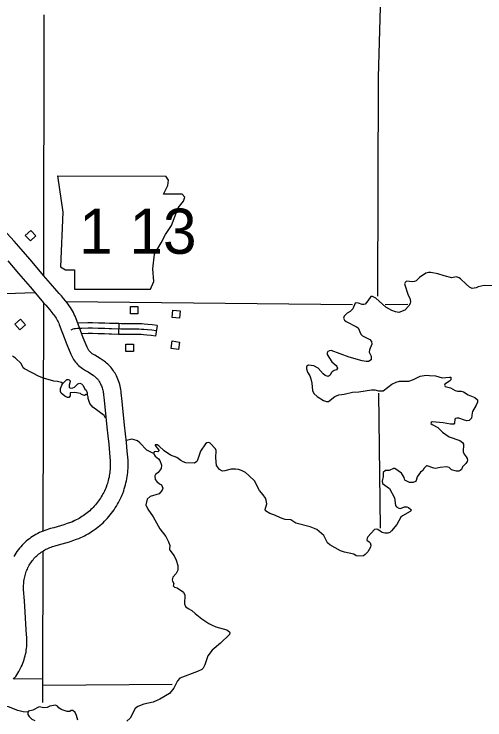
# Model space of a CAD drawing. Extents: x -19 to 366, y -4 to 359.
# Drawn here: x 133.386 to 134.638, y 199.977 to 201.853 of the extents above; entities that cross this region are included whole.
import ezdxf

# ---------------------------------------------------------------- set-up
doc = ezdxf.new("R2010")
doc.units = 0
for name, color, linetype in [('Level 10', 7, 'Continuous'), ('Level 21', 7, 'Continuous'), ('Level 32', 7, 'Continuous'), ('Level 35', 7, 'Continuous'), ('Level 4', 7, 'Continuous'), ('Level 5', 7, 'Continuous'), ('Level 56', 7, 'Continuous'), ('Level 60', 7, 'Continuous'), ('Level 9', 7, 'Continuous')]:
    doc.layers.add(name, color=color, linetype=linetype)

msp = doc.modelspace()

# ---------------------------------------------------------------- linework, layer by layer
at = {"layer": 'Level 10'}
for p, q in [((133.5147, 201.0049), (133.5148, 201.0049)), ((133.5432, 200.5044), (133.5437, 200.5046))]:
    msp.add_line(p, q, dxfattribs=at)
for points in [[(133.5591, 201.0214), (133.5575, 201.0258), (133.5501, 201.0452), (133.5482, 201.05), (133.546, 201.0548), (133.5436, 201.0595), (133.5412, 201.0642), (133.5385, 201.0687), (133.5358, 201.0732), (133.5329, 201.0776), (133.5298, 201.0819), (133.5266, 201.086), (133.5235, 201.0898), (133.5178, 201.0967), (133.512, 201.1037), (133.5059, 201.1106), (133.5, 201.1172), (133.4831, 201.1365), (133.4646, 201.1583), (133.434, 201.1941), (133.4051, 201.2284), (133.3865, 201.2494), (133.3581, 201.2803)], [(133.3693, 201.1975), (133.3979, 201.1635), (133.4285, 201.1277), (133.4472, 201.1055), (133.4647, 201.0857), (133.4705, 201.0792), (133.476, 201.0729), (133.4814, 201.0665), (133.4868, 201.0598), (133.4894, 201.0566), (133.4917, 201.0537), (133.4939, 201.0507), (133.4959, 201.0476), (133.4979, 201.0444), (133.4998, 201.0412), (133.5015, 201.0379), (133.5032, 201.0346), (133.5047, 201.0312), (133.5061, 201.0277), (133.5132, 201.0091), (133.5147, 201.0049)], [(133.5148, 201.0049), (133.5261, 200.9747), (133.5367, 200.9488), (133.5383, 200.9453), (133.5401, 200.9416), (133.5421, 200.938), (133.5444, 200.9344), (133.5467, 200.9311), (133.5492, 200.9278), (133.5519, 200.9247), (133.5547, 200.9217), (133.5576, 200.9188), (133.5607, 200.916), (133.564, 200.9135), (133.5677, 200.9108), (133.5757, 200.906), (133.5826, 200.9017), (133.5896, 200.8973), (133.5961, 200.893), (133.5979, 200.8918), (133.5996, 200.8905), (133.6013, 200.8891), (133.6029, 200.8876), (133.6045, 200.8861), (133.606, 200.8846), (133.6074, 200.883), (133.6088, 200.8813), (133.6102, 200.8796), (133.6114, 200.8778), (133.6126, 200.876), (133.6138, 200.8741), (133.6148, 200.8723), (133.6158, 200.8704), (133.617, 200.8677), (133.6182, 200.8649), (133.6193, 200.862), (133.6203, 200.8591), (133.6211, 200.8561), (133.6219, 200.8531), (133.6226, 200.8501), (133.6231, 200.847), (133.6236, 200.844), (133.6239, 200.8408), (133.6252, 200.827), (133.6327, 200.7549), (133.6353, 200.7321), (133.6376, 200.7095), (133.6397, 200.6868), (133.6416, 200.6645), (133.6418, 200.6605), (133.6418, 200.6562), (133.6418, 200.6518), (133.6416, 200.6475), (133.6414, 200.6432), (133.641, 200.639), (133.6405, 200.6347), (133.6399, 200.6304), (133.6392, 200.6261), (133.6384, 200.6219), (133.6374, 200.6177), (133.6364, 200.6135), (133.6353, 200.6093), (133.634, 200.6053), (133.6327, 200.6013), (133.6306, 200.5956), (133.6296, 200.5931), (133.628, 200.5891), (133.6262, 200.5852), (133.6244, 200.5815), (133.6224, 200.5777), (133.6202, 200.5738), (133.6179, 200.57), (133.6155, 200.5662), (133.613, 200.5625), (133.6104, 200.5588), (133.6077, 200.5552), (133.6049, 200.5517), (133.6021, 200.5482), (133.5991, 200.5449), (133.5961, 200.5415), (133.5932, 200.5385), (133.5902, 200.5357), (133.587, 200.5327), (133.5837, 200.5299), (133.5804, 200.5271), (133.5769, 200.5245), (133.5735, 200.5219), (133.5699, 200.5194), (133.5663, 200.517), (133.5626, 200.5147), (133.5589, 200.5124), (133.5551, 200.5103), (133.5513, 200.5083), (133.5474, 200.5064), (133.5432, 200.5044)], [(133.5632, 200.4615), (133.5679, 200.4637), (133.5729, 200.4662), (133.5778, 200.4688), (133.5826, 200.4715), (133.5873, 200.4743), (133.592, 200.4772), (133.5966, 200.4803), (133.6012, 200.4835), (133.6056, 200.4868), (133.6099, 200.4902), (133.6142, 200.4937), (133.6184, 200.4973), (133.6225, 200.501), (133.6267, 200.505), (133.6307, 200.5092), (133.6345, 200.5134), (133.6382, 200.5177), (133.6418, 200.522), (133.6453, 200.5265), (133.6487, 200.531), (133.6519, 200.5356), (133.6551, 200.5403), (133.6581, 200.5451), (133.6611, 200.5499), (133.6638, 200.5549), (133.6666, 200.56), (133.6691, 200.5652), (133.6714, 200.5702), (133.6735, 200.5754), (133.6749, 200.5789), (133.6774, 200.5856), (133.6791, 200.5909), (133.6808, 200.5962), (133.6822, 200.6015), (133.6835, 200.6069), (133.6847, 200.6123), (133.6858, 200.6177), (133.6867, 200.6232), (133.6875, 200.6287), (133.6881, 200.6341), (133.6886, 200.6396), (133.6889, 200.6452), (133.6891, 200.6507), (133.6892, 200.6562), (133.6891, 200.6617), (133.6889, 200.6675), (133.6869, 200.691), (133.6847, 200.7141), (133.6824, 200.7371), (133.6798, 200.76), (133.6723, 200.8316), (133.671, 200.8455), (133.6705, 200.85), (133.6698, 200.8548), (133.669, 200.8595), (133.668, 200.8641), (133.6668, 200.8687), (133.6654, 200.8733), (133.6639, 200.8778), (133.6623, 200.8822), (133.6604, 200.8867), (133.6584, 200.8911), (133.6565, 200.8947), (133.6546, 200.8982), (133.6525, 200.9015), (133.6504, 200.9048), (133.6481, 200.9079), (133.6457, 200.911), (133.6432, 200.914), (133.6406, 200.9169), (133.6378, 200.9198), (133.635, 200.9225), (133.6321, 200.9251), (133.629, 200.9276), (133.6259, 200.93), (133.6227, 200.9322), (133.6151, 200.9372), (133.6077, 200.9418), (133.6003, 200.9464), (133.5939, 200.9503), (133.5927, 200.9511), (133.5912, 200.9523), (133.5899, 200.9535), (133.5885, 200.9548), (133.5873, 200.9562), (133.5861, 200.9576), (133.5849, 200.9591), (133.5838, 200.9607), (133.5828, 200.9622), (133.5819, 200.9638), (133.5811, 200.9655), (133.5802, 200.9674), (133.5701, 200.992), (133.5591, 201.0214)], [(133.5437, 200.5046), (133.5395, 200.5028), (133.5359, 200.5013), (133.5276, 200.4985), (133.5187, 200.4957), (133.5098, 200.4929), (133.5008, 200.4902), (133.4918, 200.4877), (133.4826, 200.4852), (133.4779, 200.4839), (133.4729, 200.4823), (133.4679, 200.4806), (133.4631, 200.4787), (133.4582, 200.4766), (133.4535, 200.4745), (133.4488, 200.4721), (133.4443, 200.4696), (133.4398, 200.467), (133.4354, 200.4642), (133.431, 200.4613), (133.4268, 200.4582), (133.4227, 200.455), (133.4186, 200.4516), (133.4148, 200.4482), (133.411, 200.4446), (133.4073, 200.4408), (133.4037, 200.437), (133.4003, 200.4331), (133.3969, 200.4289), (133.3937, 200.4244), (133.3907, 200.4201), (133.3879, 200.4157), (133.3853, 200.4112)], [(133.3845, 200.0846), (133.3875, 200.0885), (133.3904, 200.0924), (133.3932, 200.0965), (133.3959, 200.1007), (133.3985, 200.105), (133.4009, 200.1093), (133.4032, 200.1138), (133.4053, 200.1182), (133.4073, 200.1226), (133.4092, 200.1273), (133.411, 200.1321), (133.4127, 200.1369), (133.4142, 200.1418), (133.4156, 200.1468), (133.4167, 200.1518), (133.4178, 200.1568), (133.4186, 200.1618), (133.4193, 200.1669), (133.4198, 200.1721), (133.4202, 200.1771), (133.4204, 200.1823), (133.4204, 200.1875), (133.4203, 200.1925), (133.42, 200.1977), (133.4195, 200.2021), (133.4175, 200.2323), (133.4154, 200.2628), (133.4135, 200.2932), (133.4115, 200.3235), (133.4114, 200.3274), (133.4113, 200.3311), (133.4114, 200.3348), (133.4116, 200.3385), (133.4119, 200.3422), (133.4123, 200.3459), (133.4128, 200.3496), (133.4135, 200.3532), (133.4143, 200.3568), (133.4152, 200.3604), (133.4162, 200.364), (133.4173, 200.3675), (133.4185, 200.371), (133.4199, 200.3744), (133.4213, 200.3778), (133.4229, 200.3812), (133.4246, 200.3845), (133.4264, 200.3877), (133.4283, 200.3909), (133.4303, 200.3941), (133.4323, 200.3971), (133.4344, 200.3999), (133.4366, 200.4026), (133.439, 200.4054), (133.4415, 200.4081), (133.4441, 200.4107), (133.4468, 200.4132), (133.4495, 200.4157), (133.4523, 200.4181), (133.4552, 200.4203), (133.4582, 200.4225), (133.4613, 200.4246), (133.4644, 200.4265), (133.4676, 200.4284), (133.4708, 200.4302), (133.4741, 200.4318), (133.4775, 200.4334), (133.4808, 200.4348), (133.4843, 200.4361), (133.4878, 200.4373), (133.4913, 200.4384), (133.4951, 200.4395), (133.5045, 200.4421), (133.514, 200.4448), (133.5235, 200.4476), (133.533, 200.4505), (133.5424, 200.4536), (133.5524, 200.4569), (133.5579, 200.4592), (133.5632, 200.4615)]]:
    msp.add_lwpolyline(points, dxfattribs=at)
at = {"layer": 'Level 21'}
for p, q in [((133.5016, 201.4227), (133.516, 201.3266)), ((133.7963, 201.4115), (133.7897, 201.4226)), ((133.7947, 201.3971), (133.7963, 201.4115)), ((133.7835, 201.3746), (133.7947, 201.3971)), ((133.8332, 201.3746), (133.7835, 201.3746)), ((133.8396, 201.3666), (133.8332, 201.3746)), ((133.8364, 201.3554), (133.8396, 201.3666)), ((133.822, 201.3378), (133.8364, 201.3554)), ((133.516, 201.3266), (133.5096, 201.1808)), ((133.814, 201.317), (133.822, 201.3378)), ((133.8043, 201.2913), (133.814, 201.317)), ((133.7883, 201.2673), (133.8043, 201.2913)), ((133.7771, 201.2449), (133.7883, 201.2673)), ((133.7595, 201.2144), (133.7771, 201.2449)), ((133.7547, 201.176), (133.7595, 201.2144)), ((133.5096, 201.1808), (133.5224, 201.1728)), ((133.7579, 201.1423), (133.7547, 201.176)), ((133.5224, 201.1728), (133.5464, 201.1728)), ((133.5464, 201.1728), (133.5464, 201.1215)), ((133.7483, 201.1215), (133.7579, 201.1423)), ((133.5464, 201.1215), (133.7483, 201.1215))]:
    msp.add_line(p, q, dxfattribs=at)
msp.add_lwpolyline([(133.5016, 201.4227), (133.7897, 201.4226)], dxfattribs=at)
at = {"layer": 'Level 32'}
for p, q in [((133.6649, 201.0301), (133.664, 201.0017)), ((133.7663, 201.0252), (133.7621, 200.9971))]:
    msp.add_line(p, q, dxfattribs=at)
for points in [[(133.6649, 201.0301), (133.6455, 201.0307), (133.6394, 201.0308), (133.6276, 201.0312), (133.6101, 201.0318), (133.5944, 201.0323), (133.5824, 201.032), (133.5555, 201.0311)], [(133.7663, 201.0252), (133.7535, 201.0271), (133.7414, 201.028), (133.7323, 201.0288), (133.7256, 201.0292), (133.718, 201.0298), (133.7108, 201.0294), (133.6989, 201.0293), (133.6855, 201.0297), (133.6704, 201.0299), (133.6649, 201.0301)], [(133.7642, 201.0112), (133.7519, 201.013), (133.7403, 201.0138), (133.7312, 201.0146), (133.7246, 201.015), (133.7178, 201.0155), (133.7112, 201.0152), (133.6987, 201.0151), (133.6852, 201.0155), (133.6701, 201.0157), (133.6451, 201.0165), (133.639, 201.0166), (133.6271, 201.017), (133.6096, 201.0176), (133.5944, 201.0181), (133.5828, 201.0178), (133.5662, 201.0173), (133.5544, 201.0168), (133.5489, 201.0167), (133.5458, 201.0162), (133.5423, 201.0155), (133.5369, 201.0132)], [(133.664, 201.0017), (133.6448, 201.0023), (133.6387, 201.0024), (133.6266, 201.0028), (133.6091, 201.0034), (133.5944, 201.0039), (133.5832, 201.0036), (133.566, 201.003)], [(133.7621, 200.9971), (133.7504, 200.9989), (133.7392, 200.9997), (133.7301, 201.0004), (133.7236, 201.0009), (133.7176, 201.0013), (133.7116, 201.001), (133.6986, 201.0009), (133.6849, 201.0013), (133.6697, 201.0015), (133.664, 201.0017)]]:
    msp.add_lwpolyline(points, dxfattribs=at)
at = {"layer": 'Level 35'}
for points in [[(133.6295, 200.779), (133.6252, 200.7858), (133.5957, 200.8081), (133.5876, 200.8179), (133.5833, 200.8311), (133.5832, 200.8353), (133.5805, 200.8413), (133.5774, 200.8416), (133.5737, 200.8393), (133.5657, 200.8422), (133.5623, 200.8445), (133.5474, 200.8473), (133.5365, 200.8464), (133.5354, 200.846), (133.5351, 200.8384), (133.5314, 200.8338), (133.528, 200.8341), (133.5211, 200.837), (133.5115, 200.8449), (133.5096, 200.8494), (133.5094, 200.8577), (133.5131, 200.8669), (133.516, 200.8707), (133.5118, 200.8733), (133.5012, 200.8762), (133.4913, 200.8772), (133.4643, 200.8856), (133.4529, 200.8896), (133.4136, 200.9103), (133.4106, 200.9129), (133.4047, 200.9238), (133.3901, 200.938), (133.3817, 200.944)], [(133.516, 200.8707), (133.522, 200.8776), (133.5261, 200.8815), (133.5299, 200.8819), (133.5329, 200.8805), (133.5349, 200.8782), (133.5353, 200.8763), (133.5324, 200.8664), (133.5325, 200.8615), (133.5352, 200.8585), (133.5423, 200.8593), (133.5465, 200.8613), (133.5558, 200.8698), (133.5607, 200.8717), (133.5653, 200.8699), (133.5699, 200.8654), (133.5738, 200.856), (133.5773, 200.8534), (133.58, 200.8458), (133.5805, 200.8413)], [(133.7566, 200.6852), (133.7394, 200.6941), (133.7206, 200.7131), (133.7141, 200.7184), (133.703, 200.7224), (133.6992, 200.7227), (133.6847, 200.7196)], [(133.4228, 199.9971), (133.4101, 199.9985), (133.3961, 200.0021), (133.3708, 200.0115), (133.3654, 200.0125), (133.3537, 200.0117), (133.3444, 200.0093), (133.3194, 199.9973), (133.3008, 199.9924), (133.2681, 199.9889), (133.2344, 199.9947), (133.2202, 199.9964), (133.2036, 199.9948), (133.1897, 199.9976)]]:
    msp.add_lwpolyline(points, dxfattribs=at)
at = {"layer": 'Level 4'}
for points in [[(133.4656, 201.1592), (133.4657, 201.8513)], [(133.4636, 200.4803), (133.4655, 201.0842)], [(133.4629, 200.0226), (133.4622, 200.0687), (133.4623, 200.087), (133.4634, 200.4243)]]:
    msp.add_lwpolyline(points, dxfattribs=at)
at = {"layer": 'Level 5'}
for points in [[(134.3528, 201.1029), (134.3551, 201.6851), (134.3662, 202.0884)], [(133.4403, 201.112), (132.4715, 201.0786)], [(133.5248, 201.0893), (134.2853, 201.0812)], [(134.3728, 201.081), (134.4331, 201.0823)], [(134.36, 200.4867), (134.3556, 200.8454)], [(133.3863, 200.0855), (133.4623, 200.087)], [(133.4622, 200.0687), (133.8062, 200.0715)]]:
    msp.add_lwpolyline(points, dxfattribs=at)
at = {"layer": 'Level 56'}
for points in [[(133.4438, 201.2636), (133.4295, 201.25), (133.4159, 201.2644), (133.4303, 201.2779)], [(133.6955, 201.0559), (133.6955, 201.0756), (133.7152, 201.0756), (133.7152, 201.0559)], [(133.8061, 201.0468), (133.808, 201.0664), (133.8277, 201.0645), (133.8258, 201.0449)], [(133.4032, 201.0417), (133.4162, 201.0269), (133.4013, 201.0138), (133.3883, 201.0287)], [(133.6833, 200.9559), (133.6833, 200.9756), (133.7031, 200.9756), (133.7031, 200.9559)], [(133.8233, 200.9617), (133.8038, 200.9645), (133.8066, 200.9841), (133.8261, 200.9813)]]:
    msp.add_lwpolyline(points, close=True, dxfattribs=at)
at = {"layer": 'Level 60'}
for points in [[(139.4406, 1.5315), (139.2511, 10.1473), (139.0608, 18.7633), (138.8699, 27.3793), (138.6784, 35.9956), (138.4861, 44.6119), (138.2932, 53.2285), (138.0997, 61.8451), (137.9055, 70.4619), (137.7106, 79.0789), (137.5151, 87.6959), (137.319, 96.3132), (137.1221, 104.9306), (136.9247, 113.5481), (136.7265, 122.1658), (136.5278, 130.7836), (136.3283, 139.4016), (136.1282, 148.0197), (135.9275, 156.6379), (135.7261, 165.2564), (135.5241, 173.8749), (135.3214, 182.4936), (135.1181, 191.1125), (134.9141, 199.7315), (134.7095, 208.3506), (134.5043, 216.9699), (134.2984, 225.5894), (134.0919, 234.209), (133.8847, 242.8288), (133.6769, 251.4487), (133.4685, 260.0687), (133.2594, 268.6889), (133.0497, 277.3093), (132.8393, 285.9298), (132.6283, 294.5504), (132.4167, 303.1713), (132.2044, 311.7922), (131.9916, 320.4133), (131.778, 329.0346), (131.5639, 337.656), (131.3491, 346.2776)], [(0, 198.1326), (7.1014, 198.137), (14.2028, 198.1503), (21.3042, 198.1724), (28.4055, 198.2034), (35.5068, 198.2433), (42.6081, 198.292), (49.7092, 198.3496), (56.8103, 198.4161), (63.9113, 198.4913), (71.0123, 198.5755), (78.1131, 198.6685), (85.2137, 198.7704), (92.3143, 198.8811), (99.4147, 199.0007), (106.5149, 199.1291), (113.615, 199.2664), (120.7149, 199.4126), (127.8146, 199.5676), (134.9141, 199.7315), (142.0135, 199.9042), (149.1125, 200.0858), (156.2114, 200.2762), (163.31, 200.4755), (170.4084, 200.6837), (177.5065, 200.9007), (184.6043, 201.1265), (191.7018, 201.3612), (198.799, 201.6048), (205.896, 201.8572), (212.9926, 202.1185), (220.0888, 202.3886), (227.1848, 202.6676), (234.2803, 202.9554), (241.3755, 203.2521), (248.4704, 203.5576), (255.5648, 203.872), (262.6589, 204.1952), (269.7525, 204.5273), (276.8457, 204.8682), (283.9385, 205.218), (291.0309, 205.5766), (298.1228, 205.9441), (305.2142, 206.3204), (312.3051, 206.7056), (319.3956, 207.0996), (326.4856, 207.5024), (333.5751, 207.9141), (340.664, 208.3347)]]:
    msp.add_spline(points, degree=3, dxfattribs=at)
at = {"layer": 'Level 9'}
for points in [[(134.6609, 201.1304), (134.6359, 201.1312), (134.6197, 201.1279), (134.6141, 201.1252), (134.6035, 201.1235), (134.5966, 201.1272), (134.5874, 201.1347), (134.5732, 201.1489), (134.569, 201.1519), (134.5614, 201.1544), (134.5497, 201.152), (134.5295, 201.157), (134.5128, 201.1628), (134.4942, 201.1664), (134.4881, 201.1659), (134.4802, 201.1639), (134.4634, 201.1526), (134.4548, 201.1442), (134.4507, 201.1422), (134.4454, 201.1414), (134.4291, 201.1427), (134.4253, 201.1392), (134.4243, 201.1362), (134.4334, 201.1059), (134.4377, 201.0977), (134.4397, 201.089), (134.4391, 201.0836), (134.4357, 201.0771), (134.4249, 201.066), (134.4088, 201.0601), (134.3997, 201.0611), (134.3905, 201.0651)], [(134.3905, 201.0651), (134.3745, 201.0736), (134.348, 201.0979), (134.3388, 201.102), (134.3343, 201.1019), (134.3265, 201.0908), (134.3191, 201.0823), (134.3157, 201.0808), (134.3115, 201.0807), (134.3013, 201.0847), (134.2971, 201.0854), (134.2926, 201.0842), (134.2867, 201.0694), (134.2793, 201.0624), (134.2718, 201.0581), (134.2639, 201.0497), (134.2617, 201.0443), (134.2645, 201.0395), (134.2687, 201.0357), (134.2965, 201.0221), (134.3011, 201.0187), (134.3078, 201.0021), (134.312, 200.9976), (134.3315, 200.9877), (134.3361, 200.9824), (134.3374, 200.976), (134.3308, 200.9607), (134.3301, 200.9543), (134.3352, 200.9433), (134.3357, 200.9369), (134.335, 200.9342), (134.3279, 200.9292), (134.3218, 200.9291), (134.3112, 200.9312), (134.2766, 200.9406), (134.2286, 200.9585), (134.2241, 200.9581), (134.2203, 200.9561), (134.2185, 200.9527), (134.2182, 200.9481), (134.2306, 200.9286), (134.2425, 200.9193), (134.2444, 200.9163), (134.2456, 200.9121), (134.243, 200.9071), (134.2366, 200.9055), (134.2314, 200.9024), (134.2291, 200.8997), (134.2262, 200.8929), (134.2213, 200.8894), (134.213, 200.8919), (134.208, 200.8964), (134.1945, 200.9114), (134.1827, 200.918), (134.169, 200.9201), (134.1645, 200.9174), (134.1634, 200.9155), (134.1631, 200.9098), (134.1659, 200.9015), (134.1721, 200.891), (134.1752, 200.8838), (134.1777, 200.8717), (134.1791, 200.8527)], [(134.1791, 200.8527), (134.183, 200.8441), (134.1915, 200.8366), (134.2087, 200.8258), (134.2167, 200.8229), (134.222, 200.8234), (134.2384, 200.8361), (134.2497, 200.8405), (134.2637, 200.8425), (134.2856, 200.8482), (134.3022, 200.8492), (134.3362, 200.8538), (134.3453, 200.8539), (134.3552, 200.8518), (134.3673, 200.8516), (134.3905, 200.8694), (134.4014, 200.8748), (134.4108, 200.8769), (134.435, 200.8772), (134.4478, 200.8819), (134.4658, 200.8905), (134.4813, 200.8934), (134.4901, 200.892), (134.506, 200.8915), (134.5238, 200.886), (134.5439, 200.8882), (134.5473, 200.8875), (134.547, 200.8807), (134.5433, 200.8768), (134.5313, 200.8695), (134.5306, 200.8664), (134.5321, 200.863), (134.5458, 200.8594), (134.5584, 200.852), (134.5649, 200.8502), (134.5747, 200.8507), (134.5804, 200.8493), (134.593, 200.8411), (134.6113, 200.8342), (134.6182, 200.8274), (134.6176, 200.821), (134.6147, 200.813), (134.6051, 200.7969), (134.6036, 200.7927), (134.6016, 200.7786), (134.596, 200.7725), (134.5899, 200.772), (134.5835, 200.7731), (134.5686, 200.7785), (134.5626, 200.7792), (134.5595, 200.7784), (134.5577, 200.7761), (134.5571, 200.7655), (134.5549, 200.7632), (134.5461, 200.7631), (134.5264, 200.7666), (134.4972, 200.7692), (134.4946, 200.7673), (134.4943, 200.765), (134.4973, 200.7624), (134.5122, 200.7539), (134.5245, 200.7415), (134.5429, 200.7296), (134.5707, 200.7198)], [(133.8357, 200.6628), (133.8296, 200.6661), (133.8185, 200.6747), (133.8021, 200.6809), (133.7849, 200.6924), (133.7711, 200.7051), (133.7661, 200.7081), (133.7615, 200.708), (133.7608, 200.7061), (133.7705, 200.6934), (133.7705, 200.6918), (133.7683, 200.6895), (133.7626, 200.6906), (133.7584, 200.689), (133.7566, 200.6852), (133.7609, 200.6777), (133.7697, 200.6706), (133.7735, 200.6661), (133.7783, 200.654), (133.7773, 200.6453), (133.7695, 200.6345), (133.762, 200.6287), (133.7602, 200.6253), (133.7611, 200.6158), (133.7657, 200.6102), (133.7726, 200.6042), (133.7779, 200.6013), (133.7815, 200.593), (133.78, 200.5876), (133.7715, 200.578), (133.7474, 200.5709), (133.7399, 200.5632), (133.7367, 200.5487), (133.7418, 200.5366), (133.7561, 200.5164), (133.7733, 200.4847), (133.7895, 200.4641), (133.7969, 200.4502), (133.7997, 200.4403), (133.7991, 200.4305), (133.8003, 200.4278), (133.8118, 200.4132), (133.8173, 200.4015), (133.8217, 200.3875), (133.8211, 200.3746), (133.8171, 200.3655), (133.8078, 200.3559), (133.806, 200.3494), (133.8072, 200.3452), (133.8111, 200.3396), (133.8093, 200.3327), (133.8127, 200.3294), (133.8196, 200.3279), (133.8368, 200.3164), (133.8399, 200.3085), (133.8395, 200.2854), (133.8419, 200.2782), (133.8488, 200.273), (133.8587, 200.2678), (133.8676, 200.2596), (133.8856, 200.2454), (133.9039, 200.2328), (133.9112, 200.2291)], [(134.3593, 200.4786), (134.3528, 200.483), (134.3483, 200.4841), (134.3441, 200.4833), (134.3266, 200.4637), (134.3244, 200.4595), (134.3241, 200.4542), (134.3302, 200.4501), (134.3322, 200.4474), (134.3342, 200.441), (134.3331, 200.4357), (134.3265, 200.4231), (134.319, 200.4162), (134.3145, 200.4131), (134.3009, 200.4121), (134.2956, 200.4132), (134.2895, 200.4169), (134.2644, 200.4226), (134.2541, 200.4259), (134.2251, 200.4421), (134.219, 200.4478), (134.2096, 200.467), (134.1912, 200.483), (134.1729, 200.49), (134.1349, 200.4997), (134.1219, 200.5082), (134.1071, 200.5099), (134.0984, 200.5124), (134.0763, 200.522), (134.0656, 200.5256), (134.0546, 200.5323), (134.0534, 200.5357), (134.0581, 200.551), (134.056, 200.5612), (134.054, 200.5665), (134.0482, 200.5747), (134.0386, 200.5863), (134.025, 200.6119), (134.0103, 200.6265), (134.0011, 200.634), (133.9908, 200.6399), (133.9825, 200.6425), (133.9745, 200.6435), (133.9632, 200.6433), (133.9462, 200.6385), (133.9401, 200.6377), (133.9318, 200.6421), (133.9244, 200.653), (133.9226, 200.6731), (133.923, 200.6925), (133.9214, 200.6974), (133.9072, 200.7127), (133.9034, 200.7142), (133.8985, 200.7134), (133.8947, 200.7107), (133.8818, 200.6911), (133.8738, 200.6671), (133.8716, 200.6633), (133.866, 200.6594), (133.8425, 200.6598), (133.8357, 200.6628)], [(134.5707, 200.7198), (134.5783, 200.7142), (134.5803, 200.71), (134.5802, 200.6892), (134.5826, 200.6828), (134.588, 200.6764), (134.5907, 200.6715), (134.5915, 200.6673), (134.5904, 200.6639), (134.5871, 200.6585), (134.5785, 200.6497), (134.5752, 200.6428), (134.5723, 200.6394), (134.5685, 200.6378), (134.5621, 200.6377), (134.5491, 200.6413), (134.5426, 200.6477), (134.5358, 200.6499), (134.5191, 200.6473), (134.5067, 200.6453), (134.5018, 200.6456), (134.4842, 200.6525), (134.482, 200.6525), (134.4764, 200.646), (134.4723, 200.6399), (134.4667, 200.6352), (134.4578, 200.6233), (134.4546, 200.6131), (134.4527, 200.6108), (134.4467, 200.6076), (134.4369, 200.6079), (134.425, 200.6142), (134.4234, 200.621), (134.4156, 200.633), (134.3981, 200.6449), (134.395, 200.6452), (134.3834, 200.6401), (134.3735, 200.6396), (134.3676, 200.6346), (134.367, 200.624), (134.3641, 200.6114), (134.365, 200.6053), (134.3837, 200.5923), (134.397, 200.5675), (134.4003, 200.547), (134.4023, 200.5429), (134.4088, 200.5392), (134.4133, 200.5389), (134.4238, 200.5428), (134.4303, 200.5429), (134.4345, 200.5414), (134.441, 200.5359), (134.4425, 200.534), (134.4388, 200.5305), (134.4189, 200.5196), (134.4144, 200.5158), (134.4034, 200.4962), (134.3892, 200.4794), (134.3847, 200.4751), (134.3799, 200.4728), (134.3719, 200.473), (134.3647, 200.4748), (134.3593, 200.4786)], [(133.9112, 200.2291), (133.9222, 200.2239), (133.9515, 200.216), (133.9591, 200.2112), (133.9599, 200.2085), (133.9585, 200.2039), (133.9346, 200.1808), (133.9122, 200.1619), (133.9007, 200.147), (133.8927, 200.123), (133.8887, 200.1146), (133.8853, 200.1111), (133.8737, 200.1053), (133.827, 200.0875), (133.8207, 200.081), (133.8104, 200.0611), (133.7989, 200.0473), (133.7738, 200.0314), (133.7561, 200.0239), (133.7308, 200.0186), (133.715, 200.0124), (133.7083, 200.0066), (133.695, 199.9813), (133.6861, 199.9729)], [(133.5554, 199.9763), (133.5522, 199.9884), (133.5483, 199.9964), (133.5426, 200.0016), (133.538, 200.0015), (133.5343, 199.9992), (133.5275, 199.9987), (133.5111, 200.0046), (133.505, 200.009), (133.5015, 200.0131), (133.4965, 200.0161), (133.4811, 200.0132), (133.4739, 200.0093), (133.4648, 200.0092), (133.4527, 200.0113), (133.4362, 200.0027), (133.4245, 199.9995), (133.4226, 199.9972), (133.4227, 199.9912), (133.4262, 199.9855), (133.4335, 199.9784), (133.4408, 199.9747)]]:
    msp.add_lwpolyline(points, dxfattribs=at)

# ---------------------------------------------------------------- texts
at = {"layer": 'Level 21'}
msp.add_text('1 13', height=0.12, dxfattribs=at).set_placement((133.5588, 201.2159))

doc.saveas('drawing.dxf')
